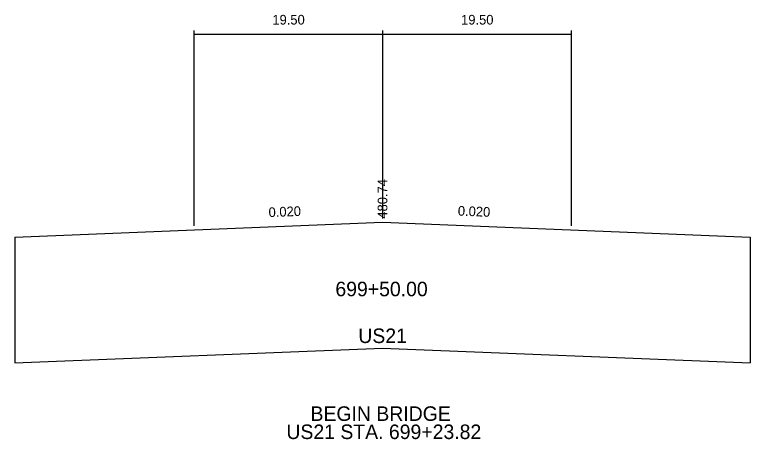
# Model space of a CAD drawing. Extents: x 2008702 to 2066449, y 841632 to 857812.
# Drawn here: x 2063158.5 to 2063234.5, y 844276.6 to 844320.4 of the extents above; entities that cross this region are included whole.
import ezdxf

# ---------------------------------------------------------------- set-up
doc = ezdxf.new("R2010")
doc.units = 0
for name, color, linetype in [('RD_PD_Bridge', 7, 'Continuous'), ('RD_XS_TX_Elev_PR', 7, 'Continuous'), ('RD_XS_TX_Misc', 7, 'Continuous'), ('RD_XS_TX_Notes', 7, 'Continuous'), ('RD_XS_TX_Slope', 7, 'Continuous'), ('RD_XS_TX_Station', 7, 'Continuous')]:
    doc.layers.add(name, color=color, linetype=linetype)

msp = doc.modelspace()

# ---------------------------------------------------------------- linework, layer by layer
at = {"layer": 'RD_PD_Bridge'}
for p, q in [((2063158.515, 844297.482), (2063196.515, 844299.002)), ((2063196.515, 844299.002), (2063234.515, 844297.482)), ((2063158.515, 844297.482), (2063158.515, 844284.482)), ((2063234.515, 844297.482), (2063234.515, 844284.482)), ((2063158.515, 844284.482), (2063196.515, 844286.002)), ((2063196.515, 844286.002), (2063234.515, 844284.482))]:
    msp.add_line(p, q, dxfattribs=at)
at = {"layer": 'RD_XS_TX_Misc'}
for p, q in [((2063177.015, 844318.802), (2063177.015, 844298.622)), ((2063177.015, 844318.402), (2063196.515, 844318.402)), ((2063196.515, 844318.802), (2063196.515, 844299.402)), ((2063196.515, 844318.402), (2063216.015, 844318.402)), ((2063216.015, 844318.802), (2063216.015, 844298.622))]:
    msp.add_line(p, q, dxfattribs=at)

# ---------------------------------------------------------------- texts
at = {"layer": 'RD_XS_TX_Elev_PR'}
msp.add_text(' 480.74', height=1, rotation=90, dxfattribs=at).set_placement((2063197.015, 844299.002))
at = {"layer": 'RD_XS_TX_Misc'}
for p in [(2063185.135, 844319.402), (2063204.635, 844319.402)]:
    msp.add_text('19.50', height=1, dxfattribs=at).set_placement(p)
at = {"layer": 'RD_XS_TX_Notes'}
for s, p in [('BEGIN BRIDGE', (2063189.08, 844278.507)), ('US21 STA. 699+23.82', (2063186.588, 844276.632))]:
    msp.add_text(s, height=1.5, dxfattribs=at).set_placement(p)
at = {"layer": 'RD_XS_TX_Slope'}
for rotation, p in [(2.29061, (2063184.764, 844299.532)), (357.70939, (2063204.284, 844299.691))]:
    msp.add_text('0.020', height=1, rotation=rotation, dxfattribs=at).set_placement(p)
at = {"layer": 'RD_XS_TX_Station'}
for s, p in [('699+50.00', (2063191.648, 844291.368)), ('US21', (2063194.016, 844286.539))]:
    msp.add_text(s, height=1.5, dxfattribs=at).set_placement(p)

doc.saveas('drawing.dxf')
